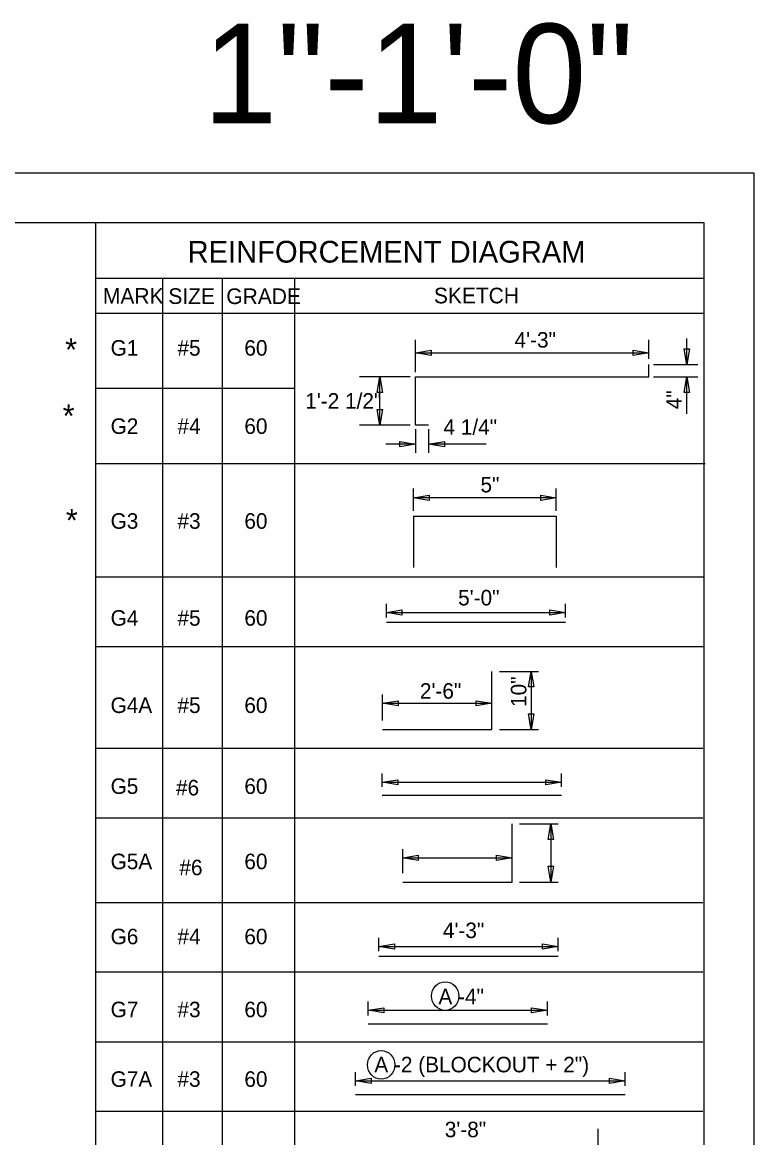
# Model space of a CAD drawing. Extents: x 0 to 34, y 0 to 23.5.
# Drawn here: x 26.65 to 34, y 12.3 to 23.51 of the extents above; entities that cross this region are included whole.
import ezdxf

# ---------------------------------------------------------------- set-up
doc = ezdxf.new("R2010")
doc.units = 0
for name, color, linetype in [('BORDER_ANNO_Cutsheet', 7, 'Continuous'), ('BRDG_ANNO_Anno-Sheet', 7, 'Continuous'), ('BRDG_ANNO_General-Notes', 7, 'Continuous'), ('BRDG_BASE_Obj-Line', 7, 'Continuous'), ('BRDG_BASE_Rebar', 7, 'Continuous'), ('Default', 7, 'Continuous')]:
    doc.layers.add(name, color=color, linetype=linetype)

# ---------------------------------------------------------------- blocks, each defined once
blk = doc.blocks.new('TERM')
at = {"layer": 'Default'}
for p, q in [((-1.6, -0.27), (-1.6, 0.27)), ((-1.6, 0.27), (0, 0)), ((0, 0), (-1.6, -0.27))]:
    blk.add_line(p, q, dxfattribs=at)

msp = doc.modelspace()

# ---------------------------------------------------------------- linework, layer by layer
at = {"layer": 'BORDER_ANNO_Cutsheet'}
msp.add_lwpolyline([(0, 22), (34, 22), (34, 0), (0, 0)], close=True, dxfattribs=at)
at = {"layer": 'BRDG_ANNO_Anno-Sheet'}
msp.add_lwpolyline([(1.5, 21.5), (33.5, 21.5), (33.5, 0.5), (1.5, 0.5)], close=True, dxfattribs=at)
at = {"layer": 'BRDG_ANNO_General-Notes'}
for p, q in [((30.601, 19.995), (30.601, 20.32)), ((32.945, 20.129), (32.945, 20.32)), ((33.329, 20.073), (33.329, 20.336)), ((30.601, 20.191), (30.759, 20.217)), ((30.759, 20.217), (30.759, 20.165)), ((32.788, 20.165), (32.788, 20.217)), ((32.788, 20.217), (32.945, 20.191)), ((33.303, 20.231), (33.356, 20.231)), ((33.329, 20.073), (33.303, 20.231)), ((33.356, 20.231), (33.329, 20.073)), ((30.601, 20.191), (32.945, 20.191)), ((30.759, 20.165), (30.601, 20.191)), ((32.945, 20.191), (32.788, 20.165)), ((32.992, 20.073), (33.439, 20.073)), ((30.547, 19.948), (30.04, 19.948)), ((30.218, 19.791), (30.244, 19.948)), ((30.244, 19.464), (30.244, 19.948)), ((30.244, 19.948), (30.271, 19.791)), ((32.992, 19.948), (33.439, 19.948)), ((33.303, 19.791), (33.329, 19.948)), ((33.329, 19.577), (33.329, 19.948)), ((33.329, 19.948), (33.356, 19.791)), ((30.271, 19.791), (30.218, 19.791)), ((33.356, 19.791), (33.303, 19.791)), ((30.218, 19.621), (30.271, 19.621)), ((30.244, 19.464), (30.218, 19.621)), ((30.271, 19.621), (30.244, 19.464)), ((30.547, 19.464), (30.04, 19.464)), ((30.601, 19.422), (30.601, 19.184)), ((30.734, 19.422), (30.734, 19.184)), ((30.444, 19.246), (30.444, 19.299)), ((30.444, 19.299), (30.601, 19.273)), ((30.734, 19.273), (30.892, 19.299)), ((30.892, 19.299), (30.892, 19.246)), ((30.601, 19.273), (30.302, 19.273)), ((30.601, 19.273), (30.444, 19.246)), ((31.311, 19.273), (30.734, 19.273)), ((30.892, 19.246), (30.734, 19.273)), ((30.583, 18.603), (30.583, 18.826)), ((32.016, 18.603), (32.016, 18.826)), ((32.016, 18.733), (30.583, 18.733)), ((30.309, 17.528), (30.309, 17.666)), ((32.11, 17.528), (32.11, 17.666)), ((30.309, 17.578), (30.466, 17.605)), ((30.309, 17.578), (32.11, 17.578)), ((30.466, 17.552), (30.309, 17.578)), ((30.466, 17.605), (30.466, 17.552)), ((31.952, 17.552), (31.952, 17.605)), ((31.952, 17.605), (32.11, 17.578)), ((32.11, 17.578), (31.952, 17.552)), ((31.445, 16.987), (31.839, 16.987)), ((31.738, 16.83), (31.764, 16.987)), ((31.764, 16.987), (31.764, 16.403)), ((31.764, 16.987), (31.791, 16.83)), ((31.791, 16.83), (31.738, 16.83)), ((30.27, 16.491), (30.27, 16.754)), ((30.27, 16.666), (30.427, 16.692)), ((30.27, 16.666), (31.37, 16.666)), ((30.427, 16.64), (30.27, 16.666)), ((30.427, 16.692), (30.427, 16.64)), ((31.213, 16.64), (31.213, 16.692)), ((31.213, 16.692), (31.37, 16.666)), ((31.37, 16.666), (31.213, 16.64)), ((31.738, 16.561), (31.791, 16.561)), ((31.764, 16.403), (31.738, 16.561)), ((31.791, 16.561), (31.764, 16.403)), ((31.445, 16.403), (31.839, 16.403)), ((30.267, 15.827), (30.267, 15.958)), ((32.068, 15.827), (32.068, 15.958)), ((30.267, 15.871), (30.424, 15.897)), ((30.267, 15.871), (32.068, 15.871)), ((30.424, 15.844), (30.267, 15.871)), ((30.424, 15.897), (30.424, 15.844)), ((31.91, 15.844), (31.91, 15.897)), ((31.91, 15.897), (32.068, 15.871)), ((32.068, 15.871), (31.91, 15.844)), ((31.648, 15.452), (32.037, 15.452)), ((31.936, 15.294), (31.962, 15.452)), ((31.962, 15.452), (31.962, 14.868)), ((31.962, 15.452), (31.988, 15.294)), ((31.988, 15.294), (31.936, 15.294)), ((30.473, 14.956), (30.473, 15.199)), ((31.573, 14.956), (31.573, 15.199)), ((30.473, 15.112), (30.63, 15.138)), ((30.473, 15.112), (31.573, 15.112)), ((30.63, 15.085), (30.473, 15.112)), ((30.63, 15.138), (30.63, 15.085)), ((31.416, 15.085), (31.416, 15.138)), ((31.416, 15.138), (31.573, 15.112)), ((31.573, 15.112), (31.416, 15.085)), ((31.936, 15.026), (31.988, 15.026)), ((31.962, 14.868), (31.936, 15.026)), ((31.988, 15.026), (31.962, 14.868)), ((31.648, 14.868), (32.037, 14.868)), ((30.234, 14.174), (30.234, 14.307)), ((32.035, 14.174), (32.035, 14.307)), ((30.234, 14.22), (30.392, 14.246)), ((30.234, 14.22), (32.035, 14.22)), ((30.392, 14.194), (30.234, 14.22)), ((30.392, 14.246), (30.392, 14.194)), ((31.877, 14.194), (31.877, 14.246)), ((31.877, 14.246), (32.035, 14.22)), ((32.035, 14.22), (31.877, 14.194)), ((30.126, 13.527), (30.126, 13.666)), ((30.126, 13.578), (30.283, 13.604)), ((30.126, 13.578), (31.927, 13.578)), ((30.283, 13.552), (30.126, 13.578)), ((30.283, 13.604), (30.283, 13.552)), ((31.769, 13.552), (31.769, 13.604)), ((31.769, 13.604), (31.927, 13.578)), ((31.927, 13.578), (31.769, 13.552)), ((31.927, 13.527), (31.927, 13.666)), ((30, 12.819), (30, 12.957)), ((32.708, 12.819), (32.708, 12.957)), ((30, 12.869), (30.157, 12.896)), ((30, 12.869), (32.708, 12.869)), ((30.157, 12.843), (30, 12.869)), ((30.157, 12.896), (30.157, 12.843)), ((32.551, 12.843), (32.551, 12.896)), ((32.551, 12.896), (32.708, 12.869)), ((32.708, 12.869), (32.551, 12.843)), ((32.437, 12.082), (32.437, 12.387))]:
    msp.add_line(p, q, dxfattribs=at)
for centre in [(30.9, 13.721), (30.256, 13.029)]:
    msp.add_ellipse(centre, major_axis=(0, 0.144), ratio=0.952381, dxfattribs=at)
at = {"layer": 'BRDG_BASE_Obj-Line'}
for p, q in [((27.387, 21.499), (27.387, 7.095)), ((27.387, 20.941), (33.506, 20.941)), ((28.06, 20.941), (28.06, 7.095)), ((28.66, 20.941), (28.66, 7.095)), ((29.386, 20.941), (29.386, 7.095)), ((27.387, 20.591), (33.5, 20.591)), ((28.059, 20.308), (28.059, 10.039)), ((27.387, 19.835), (29.386, 19.835)), ((27.387, 19.076), (33.512, 19.076)), ((27.387, 17.938), (33.494, 17.938)), ((27.387, 17.237), (33.506, 17.237)), ((27.387, 16.214), (33.488, 16.214)), ((27.387, 15.513), (33.488, 15.513)), ((27.387, 14.663), (33.488, 14.663)), ((27.387, 13.963), (33.488, 13.963)), ((27.387, 13.262), (33.488, 13.262)), ((27.387, 12.562), (33.488, 12.562))]:
    msp.add_line(p, q, dxfattribs=at)
at = {"layer": 'BRDG_BASE_Rebar'}
for p, q in [((30.583, 18.548), (32.016, 18.548)), ((30.583, 18.548), (30.583, 18.033)), ((32.016, 18.548), (32.016, 18.033)), ((30.309, 17.48), (32.11, 17.48)), ((31.37, 16.403), (31.37, 16.987)), ((30.27, 16.403), (31.37, 16.403)), ((30.267, 15.74), (32.068, 15.74)), ((31.573, 14.868), (31.573, 15.452)), ((30.473, 14.868), (31.573, 14.868)), ((30.234, 14.123), (32.035, 14.123)), ((30.126, 13.44), (31.927, 13.44)), ((30, 12.731), (32.708, 12.731))]:
    msp.add_line(p, q, dxfattribs=at)
msp.add_lwpolyline([(30.734, 19.464), (30.601, 19.464), (30.601, 19.948), (32.945, 19.948), (32.945, 20.073)], dxfattribs=at)

# ---------------------------------------------------------------- block references
at = {"layer": 'BRDG_ANNO_General-Notes', "xscale": 0.09765625, "yscale": 0.0976318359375, "rotation": 180}
msp.add_blockref('TERM', (30.583, 18.733), dxfattribs=at)
at = {"layer": 'BRDG_ANNO_General-Notes', "xscale": 0.09765625, "yscale": 0.0976318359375}
msp.add_blockref('TERM', (32.016, 18.733), dxfattribs=at)

# ---------------------------------------------------------------- texts
at = {"layer": 'BRDG_ANNO_Anno-Sheet'}
msp.add_text('1"-1\'-0"', height=1, dxfattribs=at).set_placement((28.467, 22.5))
at = {"layer": 'BRDG_ANNO_General-Notes'}
for s, height, p in [('REINFORCEMENT DIAGRAM', 0.21875, (28.312, 21.098)), ('MARK', 0.1576, (27.461, 20.684)), ('SIZE', 0.1576, (28.118, 20.682)), ('GRADE', 0.1575, (28.701, 20.681)), ('SKETCH', 0.1575, (30.787, 20.688)), ('*', 0.229, (27.081, 20.108)), ('G1', 0.1562, (27.538, 20.162)), ('#5', 0.1562, (28.21, 20.162)), ('60', 0.1562, (28.882, 20.162)), ('4\'-3"', 0.1562, (31.597, 20.243)), ('1\'-2 1/2"', 0.1562, (29.494, 19.629)), ('*', 0.229, (27.056, 19.442)), ('G2', 0.1562, (27.538, 19.375)), ('#4', 0.1562, (28.21, 19.375)), ('60', 0.1562, (28.882, 19.375)), ('4 1/4"', 0.1562, (30.883, 19.366)), ('5"', 0.1562, (31.255, 18.787)), ('*', 0.229, (27.088, 18.392)), ('G3', 0.1562, (27.538, 18.421)), ('#3', 0.1562, (28.21, 18.421)), ('60', 0.1562, (28.882, 18.421)), ('5\'-0"', 0.1562, (31.03, 17.65)), ('G4', 0.1562, (27.538, 17.446)), ('#5', 0.1562, (28.21, 17.446)), ('60', 0.1562, (28.882, 17.446)), ('2\'-6"', 0.1562, (30.646, 16.712)), ('G4A', 0.1562, (27.538, 16.568)), ('#5', 0.1562, (28.21, 16.568)), ('60', 0.1562, (28.882, 16.568)), ('G5', 0.1562, (27.538, 15.754)), ('#6', 0.1562, (28.195, 15.739)), ('60', 0.1562, (28.882, 15.754)), ('G5A', 0.1562, (27.538, 14.997)), ('60', 0.1562, (28.882, 14.997)), ('#6', 0.1562, (28.229, 14.936)), ('G6', 0.1562, (27.538, 14.242)), ('#4', 0.1562, (28.21, 14.242)), ('60', 0.1562, (28.882, 14.242)), ('4\'-3"', 0.1562, (30.877, 14.304)), ('A -4"', 0.1562, (30.832, 13.638)), ('G7', 0.1562, (27.538, 13.508)), ('#3', 0.1562, (28.21, 13.508)), ('60', 0.1562, (28.882, 13.508)), ('A -2 (BLOCKOUT + 2")', 0.15625, (30.188, 12.954)), ('G7A', 0.1562, (27.538, 12.808)), ('#3', 0.1562, (28.21, 12.808)), ('60', 0.1562, (28.882, 12.808)), ('3\'-8"', 0.1562, (30.896, 12.301))]:
    msp.add_text(s, height=height, dxfattribs=at).set_placement(p)
for s, p in [('4"', (33.278, 19.623)), ('10"', (31.716, 16.629))]:
    msp.add_text(s, height=0.1562, rotation=90, dxfattribs=at).set_placement(p)

doc.saveas('drawing.dxf')
